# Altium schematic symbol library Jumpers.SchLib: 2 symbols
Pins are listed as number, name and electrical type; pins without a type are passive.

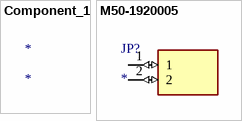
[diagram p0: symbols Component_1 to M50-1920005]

## Component_1
designator *

## M50-1920005
designator JP?
Link (Jumper); Manufacturer_Name: Harwin; Manufacturer_Part_Number: M50-1920005; Description: 1.27mm (0.05") Pitch Closed Top Jumper Socket
footprint HDRV2W100P0X508_1X2_950X320X1270P
pins: 1 (io), 2 (io)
